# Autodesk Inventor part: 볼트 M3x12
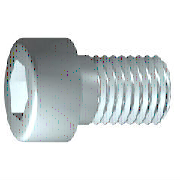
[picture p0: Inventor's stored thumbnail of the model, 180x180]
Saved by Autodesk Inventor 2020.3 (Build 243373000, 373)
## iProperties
Created: 2012-02
Part Number: 볼트 M3x12
Material: 강철, 연강
Description: 6각머리 태핑 나사
Document SubType Name: Modeling
Standard: KS B 1003
Designer: mduedu
Standards Organization: KS
Language: ko-KR
Size Designation: M 3 x 12
Categories: <MemberInstance><Categories><Category DisplayName="조임쇠" InternalName="e4da775c-781d-43d5-af7c-5136215cf5a6" Mnemonic="FSTN"><Category DisplayName="볼트" InternalN
Density: 1 g/cm^3
Appearance: 강철
IsCustomPart: 0
Author: mduedu
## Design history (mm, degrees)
sketch "스케치1"
  geometry: L1 (-0.867, 0)-(12, 0); L2 (12, 0)-(12, 1.5); L3 (12, 1.5)-(1.25, 1.5); L4 (1.25, 1.5)-(0.943, 1.5); L5 (0.943, 1.5)-(0, 1.5); L6 (0, 1.5)-(0, 2.75); L7 (0, 2.75)-(-3, 2.75); L8 (-3, 2.75)-(-3, 1.443); L9 (-3, 1.443)-(-1.7, 1.443); L10 (-1.7, 1.443)-(-0.867, 0); L11 (-6, 0)-(15, 0) reference; L12 (0, -0.55)-(0, 3.3) reference; L13 (1.25, 1.5)-(0, 1.5)
  constraints: 22 end point, 6 parallel, 2 collinear, 2 perpendicular, 1 horizontal, 1 point on line
  dimensions: "d1" = 10.75 distance from line of L3.end L2 (= GEL); "d2" = 0.30683 distance of L4.end L3.end (computed from GAL); "d3" = 3 distance between parallel lines of L8 L6 (= KOH); "d4" = 1.3 distance of L8.end L9.end (= INTI); "d5" = 60 deg angle of L10 L1; "d6" = 3 diameter of L3 L1 (= GD); "d7" = 3 diameter of L5 L1 (= BDM); "d8" = 2.88675 diameter of L9 L1 (= 1.1547 x SW); "d9" = 5.5 diameter of L7 L1 (= KOD); "d26" = 12 distance between parallel lines of L12 L2 (= NLG)
revolve "본체" sketch "스케치1" stored, may be unused: angle "d10" = 90 deg
sketch "스케치2"
  geometry: L1 (0, -3.85)-(0, 3.85) reference; L2 (-3.85, 0)-(3.85, 0) reference; L3 (1.443, 0)-(0.722, -1.25); L4 (0.722, -1.25)-(-0.722, -1.25); L5 (-0.722, -1.25)-(-1.443, 0); L6 (-1.443, 0)-(-0.722, 1.25); L7 (-0.722, 1.25)-(0.722, 1.25); L8 (0.722, 1.25)-(1.443, 0); 2 further points
  constraints: 12 end point, 1 coincident, 1 horizontal alignment, 1 point on line, 12 other
extrude "슬롯" join sketch "스케치2" stored distance "d11" = 10; taper "d12" = 0 deg
workplane "Work Plane1"
fillet "Fillet2" dims "d30" = 0.1 (= R)
body "Solid1"
fillet "모깎기1" dims "d17" = 0.3 (= RR)
feature "스레드" dims "d13" = 10.75 (= GEL), "d14" = 0
chamfer "모따기1" distance "d15" = 0.30673 (= -0.5 x SPD + 0.5 x GD); stored, may be unused: second distance "d16" = 0.30673 (= GUL), angle "d27" = 45 deg
other parameters: "GD" = 3 (= NND) [user parameter; used in 2 equation terms], "NLG" = 12 [user parameter; used in 1 equation term], "GEL" = 10.75 [user parameter; used in 2 equation terms], "KOD" = 5.5 [user parameter; used in 1 equation term], "KOH" = 3 [user parameter; used in 1 equation term], "INTI" = 1.3 [user parameter; used in 1 equation term], "GAL" = 0.30673 (= 0.61345 x PTC) [user parameter; used in 1 equation term], "GUL" = 0.30673 (= 0.61345 x PTC) [user parameter; used in 1 equation term], "BDM" = 3 (= NND) [user parameter; used in 1 equation term], "SW" = 2.5 [user parameter; used in 2 equation terms], "RR" = 0.3 [user parameter; used in 1 equation term], "SPD" = 2.38655 (= NND - 1.2269 x PTC) [user parameter; used in 1 equation term], "d19" = 0, "d28" = 0, "d29" = 0, "R" = 0.1 [user parameter; used in 1 equation term], "PHH" = 0.1 [user parameter], "GD1" = 2.38655 (= THREADDIA - 1.2269 x PTC) [user parameter], "THREADDIA" = 3 [user parameter; used in 1 equation term], "FAWI" = 45 deg [user parameter], "PTC" = 0.5 [user parameter; used in 5 equation terms], "NND" = 3 [user parameter; used in 3 equation terms], "TOA" = 30 deg [user parameter], "E0" = 2.8875 (= 1.155 x SW) [user parameter]
